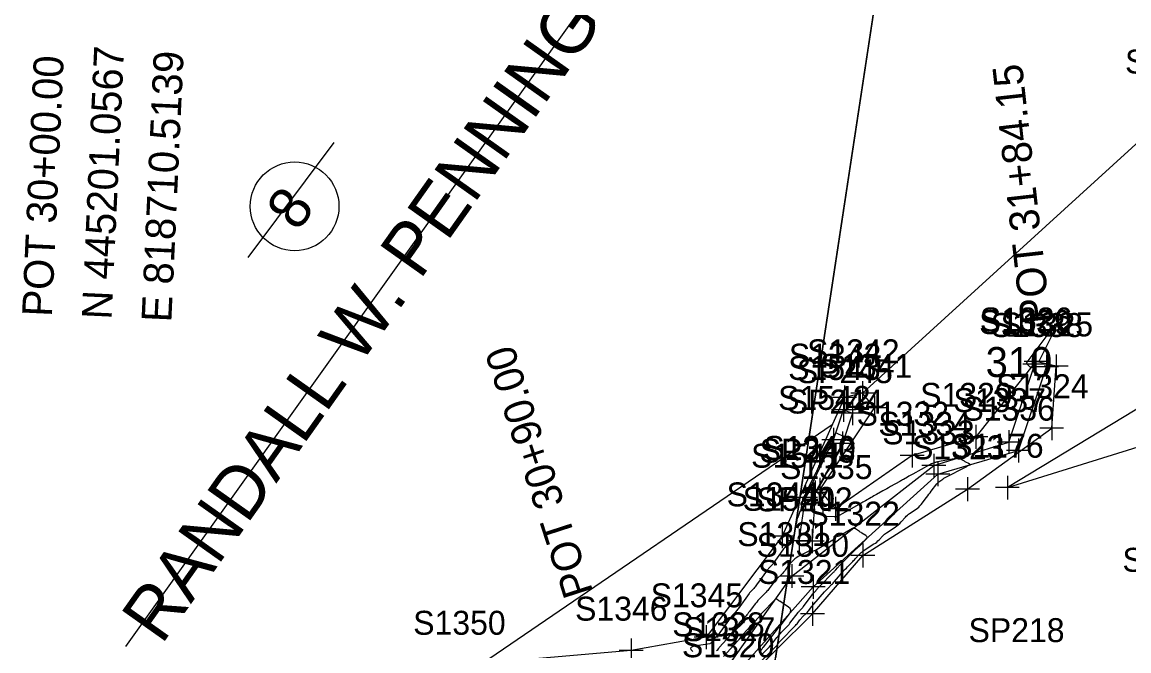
# Model space of a CAD drawing. Extents: x 816928 to 825690, y 436959 to 448212.
# Drawn here: x 818706.7 to 818891.9, y 445229.2 to 445334.3 of the extents above; entities that cross this region are included whole.
import ezdxf

# ---------------------------------------------------------------- set-up
doc = ezdxf.new("R2010")
doc.units = 0
for name, color, linetype in [('DESIGN - SCRATCH - User 1', 7, 'Continuous'), ('SURVEY - CONTOURS - Index with Text', 7, 'Continuous'), ('SURVEY - CONTOURS - Intermediate with optional Text', 7, 'Continuous'), ('SURVEY - DRAINAGE - Bridge Hydraulic Data - Points - Locators', 7, 'Continuous'), ('SURVEY - DRAINAGE - Bridge Hydraulic Data - Points - Numbers', 7, 'Continuous'), ('SURVEY - DRAINAGE - Bridge Hydraulic Data with Text', 7, 'Continuous'), ('SURVEY - DTM - Breaklines', 7, 'Continuous'), ('SURVEY - DTM - Breaklines - Points - Locators', 7, 'Continuous'), ('SURVEY - DTM - Breaklines - Points - Numbers', 7, 'Continuous'), ('SURVEY - PROPERTY - Owners', 7, 'Continuous'), ('SURVEY - PROPERTY - Parcels', 7, 'Continuous'), ('SURVEY - PROPERTY - Property Lines', 7, 'Continuous'), ('SURVEY - PROPERTY - Tract Numbers', 7, 'Continuous'), ('SURVEY - VEGETATION - Features - Points - Locators', 7, 'Continuous'), ('SURVEY - VEGETATION - Features - Points - Numbers', 7, 'Continuous'), ('SURVEY - VEGETATION - Features with Text', 7, 'Continuous')]:
    doc.layers.add(name, color=color, linetype=linetype)

msp = doc.modelspace()

# ---------------------------------------------------------------- linework, layer by layer
at = {"layer": 'DESIGN - SCRATCH - User 1'}
msp.add_lwpolyline([(818977.05, 445516.06), (818962.98, 445468.05), (818911.36, 445419.45), (818895.02, 445347.6), (818900.54, 445320.74), (818847.35, 445272.3), (818844.31, 445271.58), (818842.26, 445267.02), (818783.74, 445227.11), (818781.63, 445226.92), (818713.65, 445215.71), (818710.57, 445206.15), (818710.51, 445201.06), (818710.41, 445183.88), (818720.13, 445113.76), (818716.66, 445105.77), (818715.42, 445100.92), (818715.14, 445099.82), (818745.74, 445051.12)], dxfattribs=at)
at = {"layer": 'SURVEY - CONTOURS - Index with Text'}
msp.add_lwpolyline([(818874.87, 445277.51), (818879.03, 445283.08), (818879.63, 445283.83), (818879.89, 445284.04), (818879.82, 445283.71), (818879.42, 445282.84), (818876.81, 445277.6), (818876.79, 445277.56), (818876.76, 445277.54), (818876.73, 445277.53), (818876.69, 445277.53), (818876.54, 445277.55), (818876.51, 445277.55), (818876.49, 445277.55), (818876.47, 445277.56), (818876.44, 445277.56), (818876.37, 445277.58), (818876.36, 445277.58), (818876.34, 445277.58), (818876.33, 445277.57), (818876.32, 445277.56), (818875.67, 445276.77), (818875.57, 445276.67), (818875.46, 445276.64), (818875.36, 445276.67), (818875.25, 445276.76), (818874.89, 445277.16), (818874.83, 445277.24), (818874.81, 445277.33), (818874.82, 445277.42), (818874.87, 445277.51)], dxfattribs=at)
at = {"layer": 'SURVEY - CONTOURS - Intermediate with optional Text'}
for points in [[(818830.22, 445227.34), (818832.72, 445229.85), (818832.83, 445229.96), (818832.93, 445230.08), (818833.03, 445230.19), (818833.13, 445230.31), (818833.44, 445230.71), (818833.5, 445230.79), (818833.57, 445230.87), (818833.65, 445230.95), (818833.72, 445231.03), (818836.01, 445233.35), (818836.14, 445233.48), (818836.26, 445233.62), (818836.38, 445233.76), (818836.5, 445233.9), (818836.86, 445234.39), (818836.94, 445234.49), (818837.03, 445234.59), (818837.11, 445234.68), (818837.2, 445234.78), (818838, 445235.58), (818838.12, 445235.72), (818838.25, 445235.85), (818838.36, 445236), (818838.48, 445236.14), (818838.84, 445236.63), (818838.92, 445236.73), (818839, 445236.83), (818839.08, 445236.93), (818839.16, 445237.03), (818840.96, 445239.07), (818841.12, 445239.24), (818841.29, 445239.42), (818841.45, 445239.6), (818841.62, 445239.77), (818842.17, 445240.33), (818842.29, 445240.45), (818842.4, 445240.57), (818842.52, 445240.7), (818842.63, 445240.82), (818844.27, 445242.69), (818844.45, 445242.88), (818844.63, 445243.07), (818844.81, 445243.26), (818844.99, 445243.45), (818845.59, 445244.05), (818845.72, 445244.18), (818845.85, 445244.32), (818845.97, 445244.45), (818846.09, 445244.59), (818846.77, 445245.36), (818846.92, 445245.52), (818847.08, 445245.67), (818847.25, 445245.8), (818847.43, 445245.93), (818849.25, 445247.09), (818849.48, 445247.25), (818849.7, 445247.42), (818849.91, 445247.6), (818850.1, 445247.8), (818850.73, 445248.46), (818850.87, 445248.6), (818851.01, 445248.73), (818851.16, 445248.84), (818851.32, 445248.96), (818852.8, 445249.91), (818853.07, 445250.1), (818853.32, 445250.3), (818853.57, 445250.53), (818853.79, 445250.77), (818854.5, 445251.6), (818854.66, 445251.77), (818854.83, 445251.93), (818855.01, 445252.07), (818855.2, 445252.21), (818856.3, 445252.93), (818856.53, 445253.09), (818856.74, 445253.27), (818856.94, 445253.47), (818857.12, 445253.69), (818858.04, 445254.89), (818858.24, 445255.15), (818858.43, 445255.41), (818858.63, 445255.67), (818858.83, 445255.93), (818859.74, 445257.12), (818859.85, 445257.26), (818859.98, 445257.39), (818860.11, 445257.5), (818860.26, 445257.61), (818860.74, 445257.93), (818860.85, 445258), (818860.95, 445258.07), (818861.06, 445258.13), (818861.17, 445258.19), (818864.68, 445260), (818864.69, 445260), (818864.69, 445260), (818864.69, 445260), (818864.7, 445260), (818864.71, 445260.01), (818864.71, 445260.01), (818864.71, 445260.01), (818864.71, 445260.02), (818864.72, 445260.02), (818864.82, 445260.09), (818864.84, 445260.1), (818864.86, 445260.12), (818864.88, 445260.13), (818864.91, 445260.14), (818865.3, 445260.32), (818865.33, 445260.34), (818865.34, 445260.35), (818865.33, 445260.37), (818865.31, 445260.4), (818865.21, 445260.47), (818865.19, 445260.48), (818865.17, 445260.5), (818865.14, 445260.51), (818865.12, 445260.52), (818864.59, 445260.79), (818864.48, 445260.85), (818864.37, 445260.91), (818864.26, 445260.97), (818864.15, 445261.03), (818863.64, 445261.32), (818863.6, 445261.34), (818863.56, 445261.36), (818863.53, 445261.37), (818863.49, 445261.39), (818863.36, 445261.44), (818863.33, 445261.45), (818863.3, 445261.45), (818863.27, 445261.45), (818863.25, 445261.45), (818859.89, 445260.81), (818859.77, 445260.79), (818859.65, 445260.76), (818859.53, 445260.72), (818859.41, 445260.69), (818858.93, 445260.51), (818858.91, 445260.5), (818858.88, 445260.49), (818858.85, 445260.48), (818858.83, 445260.47), (818858.74, 445260.42), (818858.73, 445260.41), (818858.71, 445260.4), (818858.69, 445260.39), (818858.67, 445260.39), (818858.59, 445260.35), (818858.57, 445260.35), (818858.55, 445260.34), (818858.53, 445260.33), (818858.52, 445260.32), (818855.75, 445258.77), (818855.53, 445258.65), (818855.31, 445258.53), (818855.1, 445258.41), (818854.88, 445258.29), (818854.18, 445257.89), (818854.03, 445257.81), (818853.88, 445257.72), (818853.73, 445257.64), (818853.58, 445257.55), (818852.02, 445256.68), (818851.7, 445256.5), (818851.38, 445256.32), (818851.06, 445256.14), (818850.74, 445255.96), (818849.69, 445255.37), (818849.47, 445255.25), (818849.25, 445255.12), (818849.02, 445254.99), (818848.8, 445254.87), (818847.82, 445254.32), (818847.61, 445254.2), (818847.4, 445254.08), (818847.19, 445253.96), (818846.98, 445253.85), (818844.77, 445252.6), (818844.71, 445252.57), (818844.65, 445252.53), (818844.59, 445252.5), (818844.52, 445252.46), (818844.33, 445252.35), (818844.28, 445252.33), (818844.24, 445252.3), (818844.2, 445252.28), (818844.15, 445252.25), (818843.33, 445251.79), (818843.15, 445251.7), (818842.96, 445251.64), (818842.77, 445251.61), (818842.57, 445251.61), (818841.29, 445251.67), (818841.04, 445251.72), (818840.87, 445251.83), (818840.77, 445252), (818840.73, 445252.25), (818840.69, 445254.21), (818840.67, 445254.43), (818840.6, 445254.64), (818840.5, 445254.84), (818840.37, 445255.02), (818839.85, 445255.58), (818839.76, 445255.71), (818839.72, 445255.84), (818839.73, 445255.97), (818839.78, 445256.11), (818841.06, 445258.45), (818841.15, 445258.6), (818841.24, 445258.75), (818841.33, 445258.9), (818841.42, 445259.04), (818841.73, 445259.51), (818841.8, 445259.61), (818841.86, 445259.71), (818841.92, 445259.82), (818841.98, 445259.92), (818843.68, 445263.07), (818843.74, 445263.18), (818843.8, 445263.29), (818843.87, 445263.4), (818843.94, 445263.5), (818844.2, 445263.9), (818844.23, 445263.95), (818844.25, 445264), (818844.27, 445264.05), (818844.27, 445264.11), (818844.28, 445264.29), (818844.29, 445264.33), (818844.29, 445264.37), (818844.29, 445264.4), (818844.3, 445264.44), (818844.33, 445264.94), (818844.33, 445264.98), (818844.32, 445265), (818844.29, 445265.03), (818844.26, 445265.04), (818844.15, 445265.08), (818844.13, 445265.09), (818844.11, 445265.1), (818844.08, 445265.11), (818844.06, 445265.12), (818843.07, 445265.56), (818842.98, 445265.59), (818842.9, 445265.59), (818842.82, 445265.56), (818842.75, 445265.5), (818842.53, 445265.26), (818842.49, 445265.2), (818842.45, 445265.15), (818842.41, 445265.09), (818842.38, 445265.03), (818842.26, 445264.79), (818842.23, 445264.74), (818842.21, 445264.69), (818842.18, 445264.64), (818842.16, 445264.59), (818841.84, 445263.83), (818841.77, 445263.67), (818841.7, 445263.51), (818841.62, 445263.35), (818841.54, 445263.19), (818840.26, 445260.67), (818840.17, 445260.48), (818840.07, 445260.28), (818839.98, 445260.08), (818839.89, 445259.88), (818839.61, 445259.23), (818839.55, 445259.08), (818839.49, 445258.95), (818839.42, 445258.81), (818839.35, 445258.67), (818838.15, 445256.27), (818838.04, 445256.05), (818837.94, 445255.84), (818837.84, 445255.62), (818837.74, 445255.41), (818837.44, 445254.69), (818837.37, 445254.54), (818837.32, 445254.38), (818837.28, 445254.22), (818837.24, 445254.06), (818837.09, 445253.21), (818837.05, 445253.02), (818837, 445252.84), (818836.94, 445252.67), (818836.87, 445252.5), (818836.54, 445251.71), (818836.47, 445251.54), (818836.42, 445251.37), (818836.37, 445251.2), (818836.33, 445251.02), (818835.74, 445248.12), (818835.73, 445248.1), (818835.73, 445248.07), (818835.72, 445248.05), (818835.71, 445248.03), (818835.68, 445247.95), (818835.67, 445247.94), (818835.66, 445247.92), (818835.65, 445247.91), (818835.64, 445247.89), (818834.73, 445246.95), (818834.53, 445246.74), (818834.35, 445246.53), (818834.17, 445246.31), (818834.01, 445246.09), (818832.4, 445243.85), (818832.32, 445243.73), (818832.22, 445243.62), (818832.13, 445243.51), (818832.02, 445243.4), (818831.68, 445243.06), (818831.61, 445242.99), (818831.54, 445242.91), (818831.48, 445242.83), (818831.42, 445242.75), (818829.62, 445240.25), (818829.5, 445240.1), (818829.38, 445239.95), (818829.26, 445239.81), (818829.13, 445239.67), (818828.7, 445239.22), (818828.61, 445239.12), (818828.52, 445239.02), (818828.44, 445238.92), (818828.36, 445238.81), (818826.52, 445236.26), (818826.41, 445236.12), (818826.3, 445235.98), (818826.18, 445235.85), (818826.07, 445235.71), (818825.67, 445235.29), (818825.59, 445235.2), (818825.51, 445235.1), (818825.43, 445235), (818825.36, 445234.91), (818823.44, 445232.27), (818823.34, 445232.14), (818823.24, 445232), (818823.13, 445231.88), (818823.02, 445231.75), (818822.65, 445231.34), (818822.58, 445231.26), (818822.5, 445231.17), (818822.43, 445231.07), (818822.36, 445230.98), (818822.09, 445230.61), (818822.03, 445230.54), (818821.95, 445230.49), (818821.87, 445230.45), (818821.78, 445230.42), (818819.17, 445229.99), (818818.74, 445229.86), (818818.56, 445229.68), (818818.63, 445229.43), (818818.96, 445229.13)], [(818830.34, 445228.43), (818831.34, 445229.44), (818831.56, 445229.66), (818831.76, 445229.89), (818831.96, 445230.12), (818832.15, 445230.36), (818833.01, 445231.45), (818833.2, 445231.68), (818833.39, 445231.91), (818833.59, 445232.13), (818833.8, 445232.34), (818834.57, 445233.12), (818834.73, 445233.29), (818834.89, 445233.47), (818835.04, 445233.64), (818835.18, 445233.83), (818836.55, 445235.63), (818836.63, 445235.73), (818836.71, 445235.82), (818836.79, 445235.92), (818836.88, 445236.01), (818837.17, 445236.3), (818837.23, 445236.37), (818837.29, 445236.43), (818837.34, 445236.5), (818837.4, 445236.57), (818838.8, 445238.45), (818838.92, 445238.61), (818839.04, 445238.76), (818839.17, 445238.92), (818839.3, 445239.06), (818839.72, 445239.55), (818839.82, 445239.65), (818839.91, 445239.75), (818840, 445239.85), (818840.1, 445239.95), (818842.48, 445242.37), (818842.57, 445242.46), (818842.66, 445242.56), (818842.76, 445242.66), (818842.84, 445242.76), (818843.14, 445243.09), (818843.2, 445243.16), (818843.26, 445243.23), (818843.33, 445243.3), (818843.39, 445243.36), (818846.35, 445246.33), (818846.37, 445246.35), (818846.39, 445246.37), (818846.41, 445246.39), (818846.43, 445246.41), (818846.5, 445246.49), (818846.51, 445246.5), (818846.52, 445246.51), (818846.54, 445246.53), (818846.56, 445246.54), (818846.73, 445246.65), (818846.77, 445246.68), (818846.81, 445246.7), (818846.84, 445246.73), (818846.87, 445246.76), (818847.95, 445247.91), (818848.07, 445248.08), (818848.1, 445248.23), (818848.03, 445248.37), (818847.88, 445248.5), (818847.23, 445248.91), (818847.09, 445249), (818846.95, 445249.08), (818846.81, 445249.18), (818846.68, 445249.27), (818846.13, 445249.64), (818846.01, 445249.7), (818845.89, 445249.72), (818845.77, 445249.71), (818845.65, 445249.66), (818843.52, 445248.47), (818843.42, 445248.42), (818843.32, 445248.38), (818843.21, 445248.37), (818843.09, 445248.36), (818842.72, 445248.38), (818842.65, 445248.38), (818842.59, 445248.35), (818842.56, 445248.3), (818842.54, 445248.23), (818842.49, 445247.92), (818842.47, 445247.85), (818842.44, 445247.8), (818842.4, 445247.75), (818842.35, 445247.71), (818839.45, 445246.01), (818839.34, 445245.96), (818839.22, 445245.92), (818839.1, 445245.9), (818838.98, 445245.89), (818838.56, 445245.91), (818838.47, 445245.91), (818838.38, 445245.89), (818838.3, 445245.87), (818838.22, 445245.83), (818836.57, 445244.98), (818836.36, 445244.86), (818836.17, 445244.73), (818835.99, 445244.59), (818835.82, 445244.42), (818835.28, 445243.87), (818835.17, 445243.75), (818835.06, 445243.63), (818834.96, 445243.5), (818834.86, 445243.36), (818834.41, 445242.74), (818834.32, 445242.61), (818834.21, 445242.48), (818834.11, 445242.36), (818833.99, 445242.24), (818832.88, 445241.13), (818832.7, 445240.94), (818832.53, 445240.75), (818832.36, 445240.54), (818832.2, 445240.33), (818831.7, 445239.63), (818831.59, 445239.48), (818831.47, 445239.34), (818831.35, 445239.2), (818831.23, 445239.06), (818829.84, 445237.62), (818829.63, 445237.38), (818829.42, 445237.14), (818829.22, 445236.89), (818829.03, 445236.64), (818828.42, 445235.79), (818828.28, 445235.62), (818828.14, 445235.44), (818828, 445235.27), (818827.85, 445235.1), (818826.78, 445233.95), (818826.56, 445233.7), (818826.34, 445233.44), (818826.13, 445233.18), (818825.93, 445232.91), (818825.22, 445231.93), (818825.06, 445231.72), (818824.9, 445231.52), (818824.73, 445231.32), (818824.56, 445231.13), (818823.38, 445229.82), (818823.33, 445229.75), (818823.27, 445229.68), (818823.21, 445229.61), (818823.16, 445229.54), (818822.99, 445229.31), (818822.95, 445229.26), (818822.9, 445229.23)], [(818830.12, 445229.19), (818830.47, 445229.53), (818830.54, 445229.61), (818830.61, 445229.69), (818830.68, 445229.77), (818830.74, 445229.85), (818833.1, 445232.85), (818833.15, 445232.91), (818833.19, 445232.96), (818833.24, 445233.01), (818833.29, 445233.06), (818833.45, 445233.23), (818833.49, 445233.27), (818833.52, 445233.3), (818833.55, 445233.34), (818833.58, 445233.38), (818835.13, 445235.42), (818835.31, 445235.73), (818835.33, 445236.02), (818835.21, 445236.29), (818834.95, 445236.54), (818833.51, 445237.51), (818833.43, 445237.56), (818833.35, 445237.61), (818833.28, 445237.67), (818833.2, 445237.72), (818832.95, 445237.88), (818832.9, 445237.91), (818832.85, 445237.91), (818832.8, 445237.9), (818832.75, 445237.86), (818830.39, 445235.39), (818830.34, 445235.34), (818830.29, 445235.28), (818830.25, 445235.22), (818830.2, 445235.17), (818830.06, 445234.97), (818830.03, 445234.93), (818830, 445234.89), (818829.97, 445234.85), (818829.93, 445234.81), (818827.34, 445232.01), (818827.24, 445231.91), (818827.15, 445231.8), (818827.06, 445231.68), (818826.97, 445231.57), (818826.7, 445231.19), (818826.64, 445231.1), (818826.57, 445231.03), (818826.51, 445230.95), (818826.44, 445230.87), (818824.09, 445228.27)]]:
    msp.add_lwpolyline(points, dxfattribs=at)
at = {"layer": 'SURVEY - DRAINAGE - Bridge Hydraulic Data - Points - Locators'}
for p, q in [((818876.35, 445279.62), (818876.35, 445275.62)), ((818879.71, 445278.79), (818879.71, 445274.79)), ((818878.35, 445277.62), (818874.35, 445277.62)), ((818881.71, 445276.79), (818877.71, 445276.79)), ((818844.31, 445273.58), (818844.31, 445269.58)), ((818847.35, 445274.3), (818847.35, 445270.3)), ((818846.31, 445271.58), (818842.31, 445271.58)), ((818849.35, 445272.3), (818845.35, 445272.3)), ((818849.31, 445271.87), (818849.31, 445267.87)), ((818851.31, 445269.87), (818847.31, 445269.87)), ((818866.29, 445267.02), (818866.29, 445263.02)), ((818878.98, 445268.46), (818878.98, 445264.46)), ((818880.98, 445266.46), (818876.98, 445266.46)), ((818855.64, 445263.88), (818855.64, 445259.88)), ((818868.29, 445265.02), (818864.29, 445265.02)), ((818857.64, 445261.88), (818853.64, 445261.88)), ((818840.2, 445258.15), (818840.2, 445254.15)), ((818864.9, 445258.24), (818864.9, 445254.24)), ((818842.2, 445256.15), (818838.2, 445256.15)), ((818866.9, 445256.24), (818862.9, 445256.24)), ((818842.83, 445254.95), (818842.83, 445250.95)), ((818844.83, 445252.95), (818840.83, 445252.95)), ((818833.88, 445250.38), (818833.88, 445246.38)), ((818835.88, 445248.38), (818831.88, 445248.38)), ((818847.4, 445247.17), (818847.4, 445243.17)), ((818849.4, 445245.17), (818845.4, 445245.17)), ((818838.96, 445237.42), (818838.96, 445233.42)), ((818840.96, 445235.42), (818836.96, 445235.42)), ((818821.18, 445233.51), (818821.18, 445229.51)), ((818808.65, 445231.28), (818808.65, 445227.28)), ((818823.18, 445231.51), (818819.18, 445231.51)), ((818810.65, 445229.28), (818806.65, 445229.28))]:
    msp.add_line(p, q, dxfattribs=at)
at = {"layer": 'SURVEY - DRAINAGE - Bridge Hydraulic Data with Text'}
msp.add_lwpolyline([(818826.59, 445223.16), (818838.96, 445235.42), (818847.4, 445245.17), (818864.9, 445256.24), (818878.98, 445266.46), (818879.71, 445276.79), (818876.35, 445277.62), (818866.29, 445265.02), (818855.64, 445261.88), (818842.83, 445252.95), (818840.2, 445256.15), (818849.31, 445269.87), (818847.35, 445272.3), (818844.31, 445271.58), (818833.88, 445248.38), (818821.18, 445231.51), (818808.65, 445229.28), (818781.63, 445226.92)], dxfattribs=at)
at = {"layer": 'SURVEY - DTM - Breaklines'}
for points in [[(818824.83, 445226.66), (818835.52, 445241.74), (818859.27, 445260.19), (818871.83, 445264.14), (818876.15, 445277.18)], [(818826.58, 445225.85), (818839.07, 445239.95), (818859.92, 445258.75), (818873.44, 445262.71), (818878.1, 445276.69)], [(818836.74, 445247.64), (818837.82, 445254.85), (818842.5, 445264.51), (818844.17, 445269.51), (818845.63, 445268.98), (818843.97, 445263.9), (818839.41, 445255.7), (818838.9, 445247.55)]]:
    msp.add_lwpolyline(points, dxfattribs=at)
at = {"layer": 'SURVEY - DTM - Breaklines - Points - Locators'}
for p, q in [((818876.15, 445279.18), (818876.15, 445275.18)), ((818878.1, 445278.69), (818878.1, 445274.69)), ((818878.15, 445277.18), (818874.15, 445277.18)), ((818880.1, 445276.69), (818876.1, 445276.69)), ((818844.17, 445271.51), (818844.17, 445267.51)), ((818845.63, 445270.98), (818845.63, 445266.98)), ((818846.17, 445269.51), (818842.17, 445269.51)), ((818847.63, 445268.98), (818843.63, 445268.98)), ((818842.5, 445266.51), (818842.5, 445262.51)), ((818843.97, 445265.9), (818843.97, 445261.9)), ((818871.83, 445266.14), (818871.83, 445262.14)), ((818844.5, 445264.51), (818840.5, 445264.51)), ((818845.97, 445263.9), (818841.97, 445263.9)), ((818873.83, 445264.14), (818869.83, 445264.14)), ((818873.44, 445264.71), (818873.44, 445260.71)), ((818859.27, 445262.19), (818859.27, 445258.19)), ((818875.44, 445262.71), (818871.44, 445262.71)), ((818861.27, 445260.19), (818857.27, 445260.19)), ((818859.92, 445260.75), (818859.92, 445256.75)), ((818861.92, 445258.75), (818857.92, 445258.75)), ((818837.82, 445256.85), (818837.82, 445252.85)), ((818839.41, 445257.7), (818839.41, 445253.7)), ((818839.82, 445254.85), (818835.82, 445254.85)), ((818841.41, 445255.7), (818837.41, 445255.7)), ((818836.74, 445249.64), (818836.74, 445245.64)), ((818838.9, 445249.55), (818838.9, 445245.55)), ((818838.74, 445247.64), (818834.74, 445247.64)), ((818840.9, 445247.55), (818836.9, 445247.55)), ((818835.52, 445243.74), (818835.52, 445239.74)), ((818837.52, 445241.74), (818833.52, 445241.74)), ((818839.07, 445241.95), (818839.07, 445237.95)), ((818841.07, 445239.95), (818837.07, 445239.95))]:
    msp.add_line(p, q, dxfattribs=at)
at = {"layer": 'SURVEY - PROPERTY - Owners'}
for p, q in [((818724.09, 445229.94), (818832.15, 445381.21)), ((818758.9, 445314.22), (818744.51, 445295.01))]:
    msp.add_line(p, q, dxfattribs=at)
at = {"layer": 'SURVEY - PROPERTY - Parcels'}
for p, q in [((818881.31, 445547.67), (818780.72, 444885.01)), ((818815.75, 445115.79), (818881.31, 445547.67))]:
    msp.add_line(p, q, dxfattribs=at)
at = {"layer": 'SURVEY - PROPERTY - Property Lines'}
msp.add_line((818881.31, 445547.67), (818780.72, 444885.01), dxfattribs=at)
at = {"layer": 'SURVEY - PROPERTY - Tract Numbers'}
msp.add_circle((818752.33, 445303.53), 7.42, dxfattribs=at)
at = {"layer": 'SURVEY - VEGETATION - Features - Points - Locators'}
for p, q in [((818871.56, 445258.51), (818871.56, 445254.51)), ((818873.56, 445256.51), (818869.56, 445256.51))]:
    msp.add_line(p, q, dxfattribs=at)
at = {"layer": 'SURVEY - VEGETATION - Features with Text'}
msp.add_lwpolyline([(818921.65, 445531.07), (818911.36, 445419.45), (818895.02, 445347.6), (818900.54, 445320.74), (818919.8, 445285.73), (818871.56, 445256.51), (818910.14, 445268.5), (818928.96, 445242.75), (818875.35, 445097.53)], dxfattribs=at)

# ---------------------------------------------------------------- texts
at = {"layer": 'SURVEY - CONTOURS - Index with Text'}
msp.add_text('310', height=5, dxfattribs=at).set_placement((818867.93, 445275.01))
at = {"layer": 'SURVEY - DRAINAGE - Bridge Hydraulic Data - Points - Numbers'}
for s, p in [('S1326', (818866.96, 445282.62)), ('S1325', (818870.43, 445281.79)), ('S1343', (818835.02, 445276.58)), ('S1342', (818838.06, 445277.3)), ('S1341', (818840.18, 445274.87)), ('S1324', (818869.69, 445271.46)), ('S1329', (818856.98, 445270.02)), ('S1332', (818846.35, 445266.88)), ('S1340', (818830.74, 445261.15)), ('S1323', (818855.62, 445261.24)), ('S1335', (818833.54, 445257.95)), ('S1344', (818824.59, 445253.38)), ('S1322', (818838.11, 445250.17)), ('S1305', (818890.81, 445242.45)), ('S1321', (818829.83, 445240.42)), ('S1345', (818811.89, 445236.51)), ('S1346', (818799.25, 445234.28)), ('S1350', (818772.17, 445231.92)), ('SP218', (818865.07, 445230.69)), ('S1320', (818817.13, 445228.16))]:
    msp.add_text(s, height=4, dxfattribs=at).set_placement(p)
at = {"layer": 'SURVEY - DRAINAGE - Bridge Hydraulic Data with Text'}
for s, rotation, p in [('N 445201.0567', 87.3672, (818721.71, 445284.55)), ('POT 30+00.00', 87.3672, (818711.72, 445285.01)), ('E 818710.5139', 87.3672, (818731.7, 445284.09)), ('POT 31+84.15', 96.3879, (818878.85, 445284.14)), ('POT 30+90.00', 107.948, (818802.31, 445239.09))]:
    msp.add_text(s, height=5, rotation=rotation, dxfattribs=at).set_placement(p)
at = {"layer": 'SURVEY - DTM - Breaklines - Points - Numbers'}
for s, p in [('S1339', (818866.85, 445282.18)), ('S1338', (818868.76, 445281.69)), ('S1543', (818834.89, 445274.51)), ('SP245', (818836.35, 445273.98)), ('S1542', (818833.22, 445269.51)), ('SP244', (818834.68, 445268.9)), ('S1337', (818862.54, 445269.14)), ('S1336', (818864.04, 445267.71)), ('S1334', (818849.98, 445265.19)), ('S1333', (818850.63, 445263.75)), ('S1541', (818828.69, 445259.85)), ('SP243', (818830.12, 445260.7)), ('S1540', (818827.28, 445252.64)), ('SP242', (818829.61, 445252.55)), ('S1331', (818826.39, 445246.74)), ('S1330', (818829.61, 445244.95)), ('S1328', (818815.5, 445231.66)), ('S1327', (818817.29, 445230.85))]:
    msp.add_text(s, height=4, dxfattribs=at).set_placement(p)
at = {"layer": 'SURVEY - PROPERTY - Owners'}
msp.add_text('RANDALL W. PENNINGTON', height=8.75, rotation=54.6815, dxfattribs=at).set_placement((818730.08, 445230.1))
at = {"layer": 'SURVEY - PROPERTY - Tract Numbers'}
msp.add_text('8', height=7, rotation=54.6815, dxfattribs=at).set_placement((818752.89, 445299.15))
at = {"layer": 'SURVEY - VEGETATION - Features - Points - Numbers'}
for s, p in [('S1174', (818891.25, 445325.74)), ('S1176', (818862.16, 445261.51))]:
    msp.add_text(s, height=4, dxfattribs=at).set_placement(p)

doc.saveas('drawing.dxf')
